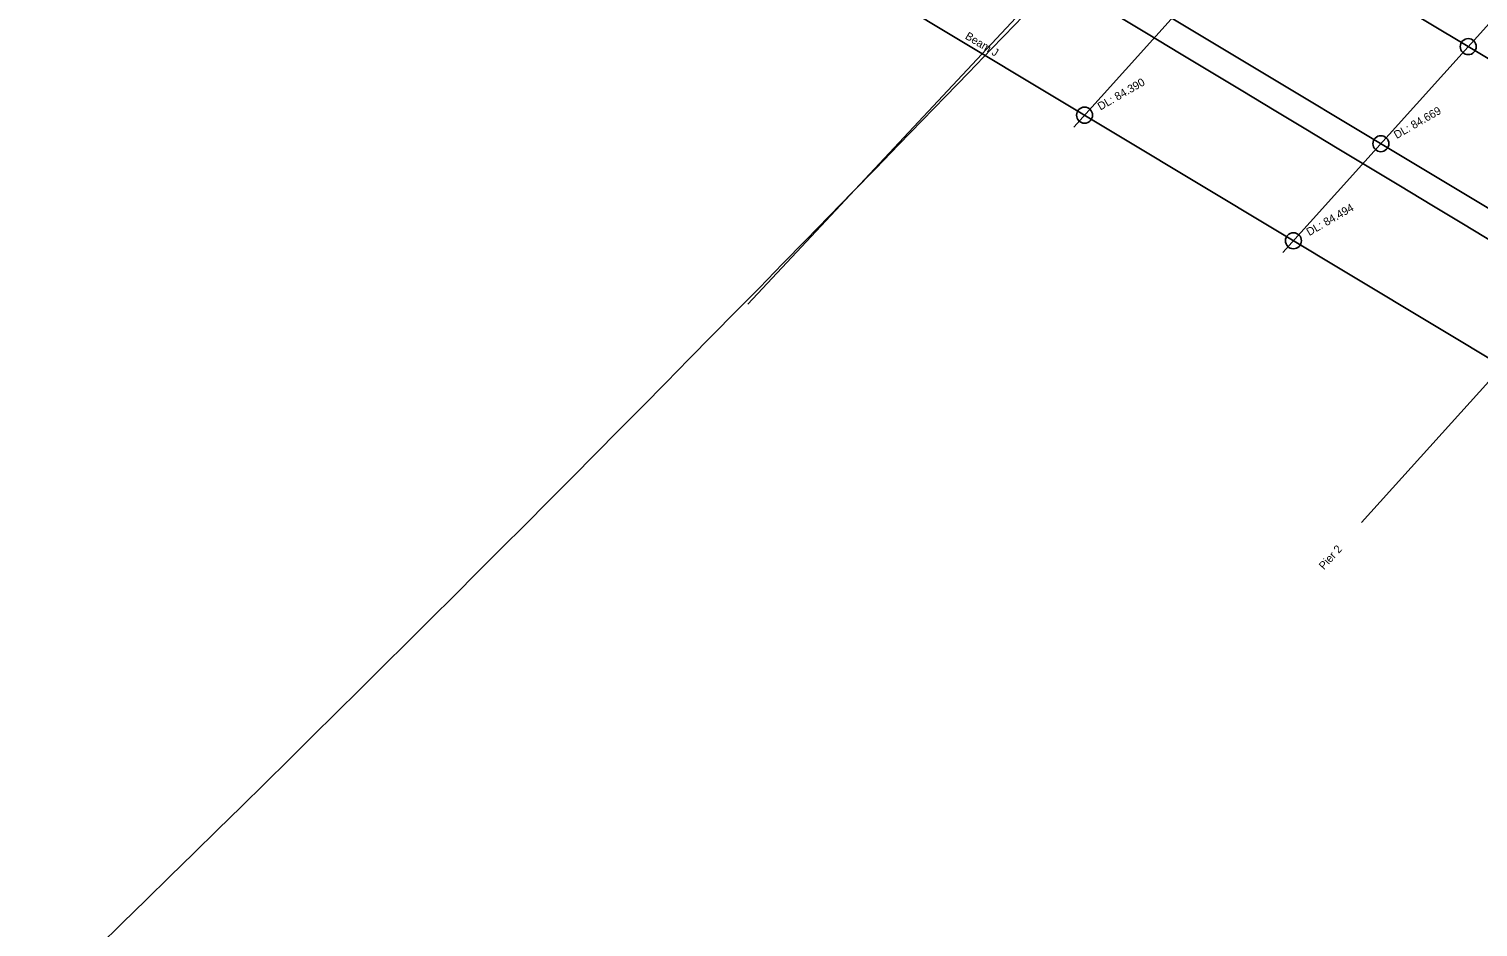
# Model space of a CAD drawing. Extents: x 3599070 to 3599898, y 342469 to 342989.
# Drawn here: x 3599529.9 to 3599620.3, y 342578.7 to 342634.7 of the extents above; entities that cross this region are included whole.
import ezdxf

# ---------------------------------------------------------------- set-up
doc = ezdxf.new("R2010")
doc.units = 0
for name, color, linetype in [('B', 7, 'Continuous'), ('EE', 7, 'Continuous'), ('GUARDRAIL', 7, 'Continuous'), ('PROLINE', 7, 'Continuous'), ('TOE', 7, 'Continuous')]:
    doc.layers.add(name, color=color, linetype=linetype)

msp = doc.modelspace()

# ---------------------------------------------------------------- linework, layer by layer
at = {"layer": 'B'}
for p, q in [((3599527.328, 342689.126), (3599673.023, 342601.535)), ((3599521.873, 342683.071), (3599667.568, 342595.48)), ((3599680.061, 342678.362), (3599613.001, 342603.921)), ((3599516.418, 342677.015), (3599662.114, 342589.424))]:
    msp.add_line(p, q, dxfattribs=at)
at = {"layer": 'EE'}
for points in [[(3599645.48, 342684.58), (3599595.048, 342628.598)], [(3599658.511, 342676.746), (3599608.079, 342620.764)]]:
    msp.add_lwpolyline(points, dxfattribs=at)
for centre in [(3599619.658, 342633.617), (3599595.718, 342629.341), (3599614.203, 342627.562), (3599608.749, 342621.507)]:
    msp.add_circle(centre, 0.499, dxfattribs=at)
at = {"layer": 'GUARDRAIL'}
msp.add_line((3599680.061, 342678.362), (3599613.001, 342603.921), dxfattribs=at)
for centre, radius, start, end in [((3594639.678, 334386.707), 9624.24, 58.9370833, 60.6876372), ((3597781.98, 344376.758), 2511.501, 311.204304, 317.276879), ((3597781.98, 344376.758), 2511.501, 311.204304, 317.276879), ((3597781.98, 344376.758), 2511.501, 311.204304, 317.276879), ((3597781.98, 344376.758), 2511.501, 311.204304, 317.276879), ((3597781.98, 344376.758), 2511.501, 311.204304, 317.276879), ((3597781.98, 344376.758), 2511.501, 311.204304, 317.276879), ((3597781.98, 344376.758), 2511.501, 311.204304, 317.276879), ((3597781.98, 344376.758), 2511.501, 311.204304, 317.276879), ((3597781.98, 344376.758), 2511.501, 311.204304, 317.276879), ((3597781.98, 344376.758), 2511.501, 311.204304, 317.276879), ((3594639.678, 334386.707), 9624.24, 57.186389, 58.9370833)]:
    msp.add_arc(centre, radius, start, end, dxfattribs=at)
at = {"layer": 'PROLINE'}
msp.add_line((3599643.565, 342691.095), (3599574.699, 342617.555), dxfattribs=at)

# ---------------------------------------------------------------- texts
at = {"layer": 'B'}
msp.add_text('Beam J', height=0.4992, rotation=328.98598, dxfattribs=at).set_placement((3599588.218, 342634.141))
at = {"layer": 'EE'}
for s, p in [('DL: 84.390', (3599596.707, 342629.624)), ('DL: 84.669', (3599615.193, 342627.845)), ('DL: 84.494', (3599609.738, 342621.79))]:
    msp.add_text(s, height=0.4992, rotation=30, dxfattribs=at).set_placement(p)
at = {"layer": 'TOE'}
msp.add_text('Pier 2', height=0.4992, rotation=47.98593, dxfattribs=at).set_placement((3599610.653, 342600.942))

doc.saveas('drawing.dxf')
